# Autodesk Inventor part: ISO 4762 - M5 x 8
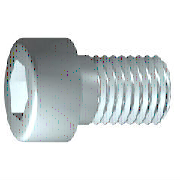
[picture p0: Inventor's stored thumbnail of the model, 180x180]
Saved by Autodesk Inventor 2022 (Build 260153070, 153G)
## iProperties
Created: 2021-02
Part Number: ISO 4762 - M5 x 8
Material: Acier inoxydable 440C
Description: Vis cylindrique à six pans creux
Document SubType Name: Modeling
Standard: ISO 4762
Designer: Fabian
Standard Revision: Fourth edition 2004-03-01
Standards Organization: ISO
Language: fr-FR
Size Designation: M5 x 8
Categories: <MemberInstance><Categories><Category DisplayName="Visserie" InternalName="e4da775c-781d-43d5-af7c-5136215cf5a6" Mnemonic="FSTN"><Category DisplayName="Vis" Int
Density: 7.75 g/cm^3
Appearance: Semi-poli
IsCustomPart: 0
Author: Fabian
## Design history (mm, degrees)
sketch "Esquisse1"
  geometry: L1 (-1.167, 0)-(8, 0); L2 (8, 0)-(8, 2.5); L3 (8, 2.5)-(2, 2.5); L4 (2, 2.5)-(1.509, 2.5); L5 (1.509, 2.5)-(0, 2.5); L6 (0, 2.5)-(0, 4.25); L7 (0, 4.25)-(-5, 4.25); L8 (-5, 4.25)-(-5, 2.309); L9 (-5, 2.309)-(-2.5, 2.309); L10 (-2.5, 2.309)-(-1.167, 0); L11 (-7.6, 0)-(10.6, 0) reference; L12 (0, -0.85)-(0, 5.1) reference; L13 (2, 2.5)-(0, 2.5)
  constraints: 22 end point, 6 parallel, 2 collinear, 2 perpendicular, 1 horizontal, 1 point on line
  dimensions: "d1" = 6 distance from line of L3.end L2 (= GEL); "d2" = 0.49086 distance of L4.end L3.end (computed from GAL); "d3" = 5 distance between parallel lines of L8 L6 (= KOH); "d4" = 2.5 distance of L8.end L9.end (= INTI); "d5" = 60 deg angle of L10 L1; "d6" = 5 diameter of L3 L1 (= GD); "d7" = 5 diameter of L5 L1 (= BDM); "d8" = 4.6188 diameter of L9 L1 (= 1.1547 x SW); "d9" = 8.5 diameter of L7 L1 (= KOD); "d26" = 8 distance between parallel lines of L12 L2 (= NLG)
revolve "Corps" sketch "Esquisse1" stored, may be unused: angle "d10" = 90 deg
sketch "Esquisse2"
  geometry: L1 (0, -5.95)-(0, 5.95) reference; L2 (-5.95, 0)-(5.95, 0) reference; L3 (2.309, 0)-(1.155, -2); L4 (1.155, -2)-(-1.155, -2); L5 (-1.155, -2)-(-2.309, 0); L6 (-2.309, 0)-(-1.155, 2); L7 (-1.155, 2)-(1.155, 2); L8 (1.155, 2)-(2.309, 0); 2 further points
  constraints: 12 end point, 1 coincident, 1 horizontal alignment, 1 point on line, 12 other
extrude "Rainure" join sketch "Esquisse2" stored distance "d11" = 10; taper "d12" = 0 deg
workplane "Work Plane1"
fillet "Fillet2" dims "d30" = 0.1 (= R)
body "Solid1"
fillet "Congé1" dims "d17" = 0.5 (= RR)
feature "Filetage" dims "d13" = 6 (= GEL), "d14" = 0
chamfer "Chanfrein1" distance "d15" = 0.49076 (= -0.5 x SPD + 0.5 x GD); stored, may be unused: second distance "d16" = 0.49076 (= GUL), angle "d27" = 45 deg
other parameters: "GD" = 5 [user parameter; used in 2 equation terms], "NLG" = 8 [user parameter; used in 1 equation term], "GEL" = 6 [user parameter; used in 2 equation terms], "KOD" = 8.5 [user parameter; used in 1 equation term], "KOH" = 5 [user parameter; used in 1 equation term], "INTI" = 2.5 [user parameter; used in 1 equation term], "GAL" = 0.49076 (= 0.61345 x PTC) [user parameter; used in 1 equation term], "GUL" = 0.49076 (= 0.61345 x PTC) [user parameter; used in 1 equation term], "BDM" = 5 (= NND) [user parameter; used in 1 equation term], "SW" = 4 [user parameter; used in 2 equation terms], "RR" = 0.5 [user parameter; used in 1 equation term], "SPD" = 4.01848 (= NND - 1.2269 x PTC) [user parameter; used in 1 equation term], "d19" = 0, "d28" = 0, "d29" = 0, "R" = 0.1 [user parameter; used in 1 equation term], "TOA" = 30 deg [user parameter], "GD1" = 4.01848 (= THREADDIA - 1.2269 x PTC) [user parameter], "THREADDIA" = 5 [user parameter; used in 1 equation term], "FAWI" = 45 deg [user parameter], "TPU" = 12.5 (computed from PTC) [user parameter], "PTC" = 0.8 [user parameter; used in 5 equation terms], "NND" = 5 [user parameter; used in 2 equation terms], "E0" = 4.62 (= 1.155 x SW) [user parameter]
